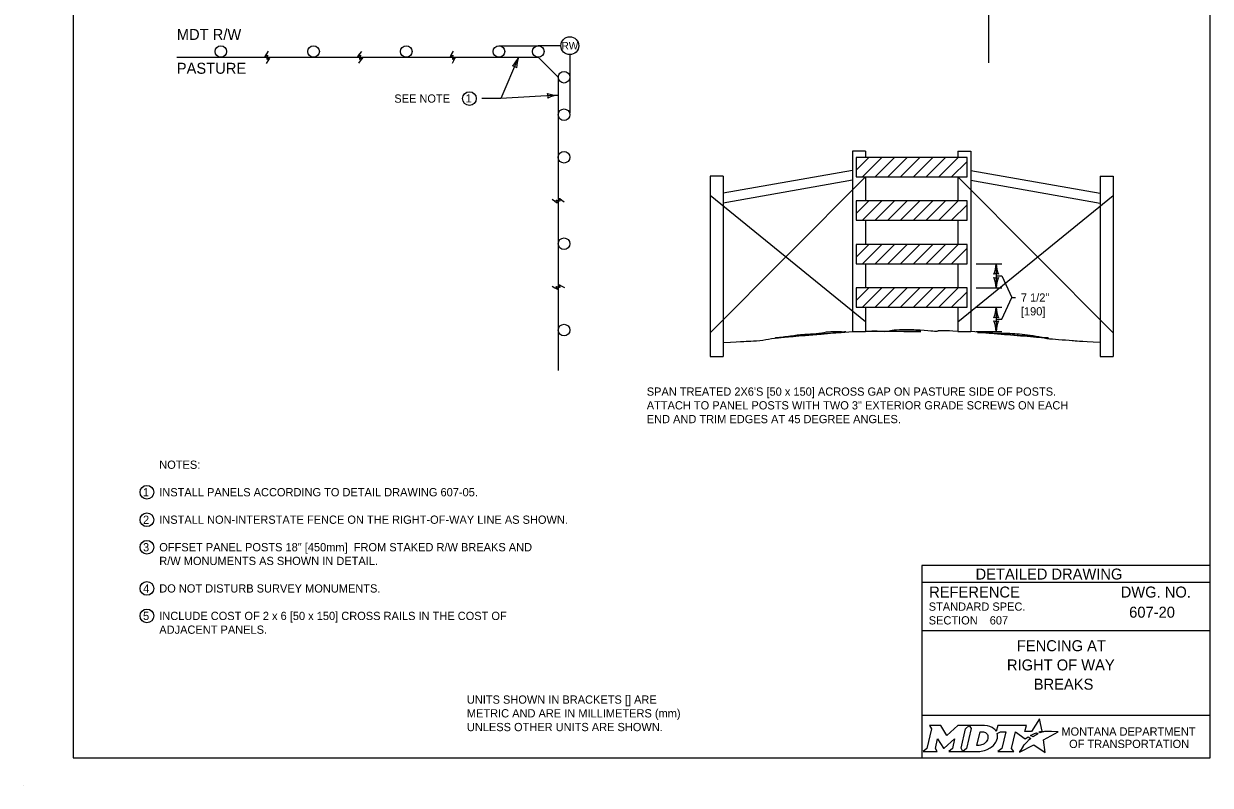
# Model space of a CAD drawing. Extents: x 49991.4 to 50021, y 49987.6 to 50011.4.
# Drawn here: x 49999.98 to 50008.61, y 49999.86 to 50005.41 of the extents above; entities that cross this region are included whole.
import ezdxf

# ---------------------------------------------------------------- set-up
doc = ezdxf.new("R2010")
doc.units = 0
for name, color, linetype in [('Default', 7, 'Continuous'), ('Level 1', 7, 'Continuous'), ('Level 2', 7, 'Continuous'), ('Level 3', 7, 'Continuous'), ('Level 5', 7, 'Continuous')]:
    doc.layers.add(name, color=color, linetype=linetype)

msp = doc.modelspace()

# ---------------------------------------------------------------- linework, layer by layer
at = {"layer": 'Default'}
msp.add_line((50003.9521, 50005.2464), (50003.9521, 50005.2464), dxfattribs=at)
msp.add_circle((50003.9521, 50005.2464), 0.0653, dxfattribs=at)
at = {"layer": 'Level 1'}
for p, q in [((50007.0001, 50006.2278), (50007.0001, 50005.1218)), ((50003.4364, 50005.2464), (50003.7227, 50005.2464)), ((50001.0908, 50005.162), (50003.7227, 50005.162)), ((50003.8677, 50005.017), (50003.7227, 50005.162)), ((50003.8677, 50005.017), (50003.8677, 50002.881)), ((50003.9521, 50005.017), (50003.9521, 50004.7565)), ((50006.0109, 50004.4791), (50006.0109, 50003.1666)), ((50006.1047, 50004.4791), (50006.0109, 50004.4791)), ((50006.13, 50004.4322), (50006.0378, 50004.34)), ((50006.2228, 50004.4322), (50006.0822, 50004.2916)), ((50006.1047, 50004.4791), (50006.1047, 50004.4322)), ((50006.3156, 50004.4322), (50006.175, 50004.2916)), ((50006.4084, 50004.4322), (50006.2678, 50004.2916)), ((50006.5012, 50004.4322), (50006.3606, 50004.2916)), ((50006.594, 50004.4322), (50006.4534, 50004.2916)), ((50006.6868, 50004.4322), (50006.5462, 50004.2916)), ((50006.7796, 50004.4322), (50006.639, 50004.2916)), ((50006.7776, 50004.4791), (50006.8713, 50004.4791)), ((50006.7776, 50004.4791), (50006.7776, 50004.4322)), ((50006.8713, 50004.4791), (50006.8713, 50003.1666)), ((50006.8445, 50004.4043), (50006.7318, 50004.2916)), ((50005.068, 50004.2962), (50004.9743, 50004.2962)), ((50004.9743, 50004.2962), (50004.9743, 50002.9837)), ((50004.9743, 50003.1564), (50006.1047, 50004.2916)), ((50006.0109, 50004.3384), (50005.068, 50004.1721)), ((50005.068, 50004.2962), (50005.068, 50002.9837)), ((50006.0109, 50004.267), (50005.068, 50004.1007)), ((50006.1047, 50004.2916), (50006.1047, 50004.1158)), ((50006.7776, 50004.2916), (50006.7776, 50004.1158)), ((50007.908, 50003.1564), (50006.7776, 50004.2916)), ((50006.8713, 50004.3384), (50007.8142, 50004.1721)), ((50006.8713, 50004.267), (50007.8142, 50004.1007)), ((50007.8142, 50004.2962), (50007.908, 50004.2962)), ((50007.8142, 50004.2962), (50007.8142, 50002.9837)), ((50007.908, 50004.2962), (50007.908, 50002.9837)), ((50006.1047, 50003.2364), (50004.9743, 50004.1556)), ((50006.13, 50004.1158), (50006.0378, 50004.0236)), ((50006.2228, 50004.1158), (50006.0822, 50003.9752)), ((50006.3156, 50004.1158), (50006.175, 50003.9752)), ((50006.4084, 50004.1158), (50006.2678, 50003.9752)), ((50006.5012, 50004.1158), (50006.3606, 50003.9752)), ((50006.594, 50004.1158), (50006.4534, 50003.9752)), ((50006.6868, 50004.1158), (50006.5462, 50003.9752)), ((50006.7796, 50004.1158), (50006.639, 50003.9752)), ((50006.8445, 50004.0879), (50006.7318, 50003.9752)), ((50006.7776, 50003.2364), (50007.908, 50004.1556)), ((50006.1047, 50003.9752), (50006.1047, 50003.7994)), ((50006.7776, 50003.9752), (50006.7776, 50003.7994)), ((50006.13, 50003.7994), (50006.0378, 50003.7072)), ((50006.2228, 50003.7994), (50006.0822, 50003.6588)), ((50006.3156, 50003.7994), (50006.175, 50003.6588)), ((50006.4084, 50003.7994), (50006.2678, 50003.6588)), ((50006.5012, 50003.7994), (50006.3606, 50003.6588)), ((50006.594, 50003.7994), (50006.4534, 50003.6588)), ((50006.6868, 50003.7994), (50006.5462, 50003.6588)), ((50006.7796, 50003.7994), (50006.639, 50003.6588)), ((50006.8445, 50003.7715), (50006.7318, 50003.6588)), ((50006.1047, 50003.6588), (50006.1047, 50003.483)), ((50006.7776, 50003.6588), (50006.7776, 50003.483)), ((50006.13, 50003.483), (50006.0378, 50003.3908)), ((50006.2228, 50003.483), (50006.0822, 50003.3424)), ((50006.3156, 50003.483), (50006.175, 50003.3424)), ((50006.4084, 50003.483), (50006.2678, 50003.3424)), ((50006.5012, 50003.483), (50006.3606, 50003.3424)), ((50006.594, 50003.483), (50006.4534, 50003.3424)), ((50006.6868, 50003.483), (50006.5462, 50003.3424)), ((50006.7796, 50003.483), (50006.639, 50003.3424)), ((50006.8445, 50003.4551), (50006.7318, 50003.3424)), ((50006.1047, 50003.3424), (50006.1047, 50003.1666)), ((50006.7776, 50003.3424), (50006.7776, 50003.1666)), ((50006.0109, 50003.1666), (50006.1047, 50003.1666)), ((50006.7776, 50003.1666), (50006.8713, 50003.1666)), ((50004.9743, 50002.9837), (50005.068, 50002.9837)), ((50007.8142, 50002.9837), (50007.908, 50002.9837)), ((49999.9766, 49999.8624), (49999.9766, 49999.8624))]:
    msp.add_line(p, q, dxfattribs=at)
for points in [[(50008.6146, 50011.2628), (50000.3356, 50011.2628), (50000.3356, 50000.0624), (50008.6146, 50000.0624)], [(50006.0378, 50004.4322), (50006.0378, 50004.2916), (50006.8445, 50004.2916), (50006.8445, 50004.4322)], [(50006.0378, 50004.1158), (50006.0378, 50003.9752), (50006.8445, 50003.9752), (50006.8445, 50004.1158)], [(50006.0378, 50003.7994), (50006.0378, 50003.6588), (50006.8445, 50003.6588), (50006.8445, 50003.7994)], [(50006.0378, 50003.483), (50006.0378, 50003.3424), (50006.8445, 50003.3424), (50006.8445, 50003.483)]]:
    msp.add_lwpolyline(points, close=True, dxfattribs=at)
for centre in [(50001.4114, 50005.2042), (50002.0864, 50005.2042), (50002.7614, 50005.2042), (50003.4364, 50005.2042), (50003.7227, 50005.2042), (50003.9099, 50005.017), (50003.9099, 50004.744), (50003.9098, 50004.4338), (50003.9099, 50003.8049), (50003.91, 50003.176)]:
    msp.add_circle(centre, 0.0422, dxfattribs=at)
for points in [[(50001.7556, 50005.2058), (50001.7337, 50005.164), (50001.7509, 50005.1769), (50001.7467, 50005.1466), (50001.7639, 50005.1594), (50001.7422, 50005.1174)], [(50002.4347, 50005.2053), (50002.4091, 50005.1658), (50002.4274, 50005.1769), (50002.4203, 50005.1472), (50002.4387, 50005.1583), (50002.4132, 50005.1185)], [(50003.1018, 50005.2062), (50003.0836, 50005.1627), (50003.0997, 50005.177), (50003.098, 50005.1464), (50003.1141, 50005.1607), (50003.096, 50005.117)], [(50003.8241, 50004.1286), (50003.8646, 50004.1044), (50003.8528, 50004.1223), (50003.8828, 50004.1164), (50003.8709, 50004.1343), (50003.9116, 50004.1103)], [(50003.8234, 50003.4948), (50003.8663, 50003.4752), (50003.8525, 50003.4918), (50003.883, 50003.4891), (50003.8693, 50003.5057), (50003.9124, 50003.4862)]]:
    msp.add_spline(points, degree=3, dxfattribs=at)
for points in [[(50005.068, 50003.0861), (50005.2257, 50003.0938), (50005.2638, 50003.0965), (50005.3597, 50003.1007), (50005.438, 50003.1194), (50005.546, 50003.131), (50005.6474, 50003.1474), (50005.7209, 50003.1464), (50005.8113, 50003.1608), (50005.8633, 50003.1685), (50005.9543, 50003.163), (50006.0109, 50003.1666), (50005.068, 50003.0861), (50006.0109, 50003.1666)], [(50006.7776, 50003.1666), (50006.7203, 50003.1698), (50006.6815, 50003.1712), (50006.6377, 50003.1706), (50006.6366, 50003.1706), (50006.632, 50003.1695), (50006.6241, 50003.1662), (50006.6101, 50003.1655), (50006.5111, 50003.176), (50006.3666, 50003.1804), (50006.29, 50003.1724), (50006.2627, 50003.1638), (50006.2187, 50003.1645), (50006.1633, 50003.1707), (50006.1047, 50003.1666), (50006.7776, 50003.1666), (50006.1047, 50003.1666)], [(50007.8142, 50003.0861), (50007.6565, 50003.0938), (50007.6185, 50003.0965), (50007.5051, 50003.1066), (50007.4242, 50003.1104), (50007.3479, 50003.132), (50007.2604, 50003.1428), (50007.1917, 50003.1489), (50007.1175, 50003.1523), (50007.0314, 50003.1498), (50006.927, 50003.1571), (50006.8713, 50003.1666), (50007.8142, 50003.0861), (50006.8713, 50003.1666)]]:
    msp.add_open_spline(points, degree=3, dxfattribs=at)
at = {"layer": 'Level 2'}
for p, q in [((50008.6146, 50001.4624), (50006.5146, 50001.4624)), ((50006.5146, 50001.4624), (50006.5146, 50000.0624)), ((50008.6146, 50001.3374), (50006.5146, 50001.3374)), ((50008.2507, 50001.1223), (50008.2507, 50001.1223)), ((50008.6146, 50000.9874), (50006.5146, 50000.9874)), ((50007.0089, 50001.0629), (50007.0089, 50001.0629)), ((50007.5646, 50000.7383), (50007.5646, 50000.7383)), ((50008.6146, 50000.3693), (50006.5146, 50000.3693))]:
    msp.add_line(p, q, dxfattribs=at)
for points in [[(50006.5701, 50000.2974), (50006.5842, 50000.274), (50006.5507, 50000.1307), (50006.525, 50000.1082), (50006.6266, 50000.1082), (50006.6131, 50000.131), (50006.6293, 50000.2011), (50006.673, 50000.1321), (50006.6783, 50000.1321), (50006.7534, 50000.2016), (50006.737, 50000.1305), (50006.7123, 50000.1085), (50006.8139, 50000.1085), (50006.8001, 50000.1318), (50006.8333, 50000.2742)], [(50006.8333, 50000.2742), (50006.8586, 50000.2974), (50006.7762, 50000.2974), (50006.6966, 50000.2244), (50006.6521, 50000.2971), (50006.5701, 50000.2974)], [(50006.9722, 50000.2974), (50006.8586, 50000.2974), (50006.8733, 50000.2745), (50006.8394, 50000.1307), (50006.8139, 50000.1085), (50006.9245, 50000.1085)], [(50007.3771, 50000.2447), (50007.3668, 50000.2503), (50007.3784, 50000.2531), (50007.39, 50000.2551), (50007.3726, 50000.3452), (50007.3131, 50000.2539), (50007.2658, 50000.2532), (50007.2761, 50000.2973), (50007.0669, 50000.2974), (50007.0568, 50000.2549), (50007.051, 50000.2632)], [(50006.9962, 50000.2107), (50006.995, 50000.2026), (50006.9918, 50000.1933), (50006.9876, 50000.1851), (50006.982, 50000.1776), (50006.9755, 50000.1707), (50006.9676, 50000.1644), (50006.9593, 50000.1597), (50006.9502, 50000.1558), (50006.9411, 50000.1535), (50006.9319, 50000.1526), (50006.916, 50000.1526), (50006.9396, 50000.2526), (50006.9556, 50000.2526), (50006.9632, 50000.252), (50006.9708, 50000.2501), (50006.9774, 50000.2471), (50006.9835, 50000.2429), (50006.9883, 50000.2379), (50006.992, 50000.2319), (50006.9947, 50000.2257), (50006.9963, 50000.2183), (50006.9963, 50000.2153), (50006.9962, 50000.2107)], [(50007.0636, 50000.2383), (50007.0882, 50000.2514), (50007.1251, 50000.2514), (50007.0965, 50000.1309), (50007.069, 50000.1082), (50007.1852, 50000.1082), (50007.1682, 50000.1311), (50007.1964, 50000.2513), (50007.2677, 50000.1996), (50007.2888, 50000.2147), (50007.3085, 50000.2038)], [(50007.2527, 50000.1479), (50007.2374, 50000.1235), (50007.2327, 50000.116), (50007.2269, 50000.1074), (50007.2246, 50000.1031), (50007.3299, 50000.1562), (50007.4138, 50000.1011), (50007.4007, 50000.1938), (50007.5076, 50000.2522), (50007.4583, 50000.253), (50007.4282, 50000.2534), (50007.4074, 50000.2537), (50007.4006, 50000.2522), (50007.3957, 50000.251), (50007.3873, 50000.2487), (50007.3771, 50000.2447)], [(50007.3267, 50000.2171), (50007.3243, 50000.2154), (50007.306, 50000.225), (50007.3163, 50000.2307), (50007.3204, 50000.2329), (50007.329, 50000.2369), (50007.3347, 50000.2395), (50007.3426, 50000.2425), (50007.3499, 50000.2452), (50007.3617, 50000.2378), (50007.3577, 50000.2357), (50007.3531, 50000.2332), (50007.3489, 50000.231), (50007.3439, 50000.2281), (50007.342, 50000.227), (50007.3393, 50000.2254), (50007.3368, 50000.224), (50007.3345, 50000.2224), (50007.3319, 50000.2206), (50007.3292, 50000.2188), (50007.3267, 50000.2171)], [(50006.9702, 50000.1158), (50006.9786, 50000.1184), (50006.9916, 50000.1238), (50007.012, 50000.1348)], [(50007.2666, 50000.164), (50007.2666, 50000.164)]]:
    msp.add_lwpolyline(points, dxfattribs=at)
for centre in [(50003.2213, 50004.8615), (50000.8732, 50001.9955), (50000.8732, 50001.7954), (50000.8732, 50001.5953), (50000.8732, 50001.2951), (50000.8732, 50001.0953)]:
    msp.add_circle(centre, 0.05, dxfattribs=at)
for centre, radius, start, end in [((50006.9953, 50000.219), 0.0709, 339.53292, 15.85821), ((50006.9513, 50000.2363), 0.1183, 300.91025, 339.13831)]:
    msp.add_arc(centre, radius, start, end, dxfattribs=at)
for centre, major_axis, ratio, start_param, end_param in [((50006.9701, 50000.25), (0.0834, -0.0037), 0.568097, 0.61298, 1.570796), ((50007.0257, 50000.2573), (0.0361, -0.0295), 0.469099, 1.225588, 1.570796), ((50007.2974, 50000.1941), (-0.0112, -0.0097), 0.021651, 3.157348, 6.283185), ((50006.9248, 50000.2568), (0, 0.1484), 0.987302, 3.139398, 3.456847), ((50007.2597, 50000.1559), (-0.00694, -0.00806), 0.008222, 0, 3.137361), ((50007.2764, 50000.1742), (-0.0098, -0.0102), 0.016458, 3.141593, 6.279097)]:
    msp.add_ellipse(centre, major_axis=major_axis, ratio=ratio, start_param=start_param, end_param=end_param, dxfattribs=at)
at = {"layer": 'Level 3'}
for p, q in [((50003.8868, 50005.2464), (50003.7227, 50005.2464)), ((50003.5795, 50005.162), (50003.45, 50004.8615)), ((50003.9521, 50005.181), (50003.9521, 50005.017)), ((50003.8677, 50004.8867), (50003.45, 50004.8615)), ((50003.45, 50004.8615), (50003.3113, 50004.8615)), ((50006.9113, 50003.6588), (50007.0961, 50003.6588)), ((50007.0561, 50003.6588), (50007.0561, 50003.483)), ((50006.9113, 50003.483), (50007.0961, 50003.483)), ((50007.169, 50003.4127), (50007.1959, 50003.4127)), ((50006.9113, 50003.3424), (50007.0961, 50003.3424)), ((50007.0561, 50003.3424), (50007.0561, 50003.1666)), ((50006.9113, 50003.1666), (50007.0961, 50003.1666))]:
    msp.add_line(p, q, dxfattribs=at)
for points in [[(50007.0561, 50003.5709), (50007.0961, 50003.5709), (50007.169, 50003.4127)], [(50007.0561, 50003.2545), (50007.0961, 50003.2545), (50007.169, 50003.4127)]]:
    msp.add_lwpolyline(points, dxfattribs=at)
for centre, radius, start, end in [((50003.3792, 50005.2583), 0.2223, 314.14194, 334.32545), ((50003.7978, 50005.0804), 0.233, 159.51324, 178.76309), ((50003.5288, 50005.0442), 0.0548, 48.82475, 84.54711), ((50003.8635, 50005.109), 0.2223, 250.91163, 271.09514), ((50003.7397, 50004.879), 0.0548, 345.59444, 21.3168), ((50003.8932, 50004.6551), 0.233, 96.28293, 115.53278), ((50006.8339, 50003.6679), 0.2223, 337.45601, 357.63952), ((50007.2888, 50003.6703), 0.233, 182.82731, 202.07716), ((50007.0561, 50003.5305), 0.0548, 72.13882, 107.86118), ((50007.0561, 50003.6112), 0.0548, 252.13882, 287.86118), ((50006.8234, 50003.4715), 0.233, 2.82731, 22.07716), ((50007.2782, 50003.4738), 0.2223, 157.45601, 177.63952), ((50006.8339, 50003.3515), 0.2223, 337.45601, 357.63952), ((50007.2888, 50003.3538), 0.233, 182.82731, 202.07716), ((50007.0561, 50003.2141), 0.0548, 72.13882, 107.86118), ((50007.0561, 50003.2948), 0.0548, 252.13882, 287.86118), ((50006.8234, 50003.1551), 0.233, 2.82731, 22.07716), ((50007.2782, 50003.1574), 0.2223, 157.45601, 177.63952)]:
    msp.add_arc(centre, radius, start, end, dxfattribs=at)

# ---------------------------------------------------------------- texts
at = {"layer": 'Level 2'}
for s, height, p in [('MDT R/W', 0.08, (50001.0908, 50005.2884)), ('RW', 0.054, (50003.8925, 50005.2192)), ('PASTURE', 0.08, (50001.0908, 50005.042)), ('SEE NOTE', 0.06, (50002.6744, 50004.8315)), ('1', 0.06, (50003.1937, 50004.833)), ('7 1/2"', 0.06, (50007.2359, 50003.3827)), ('[190]', 0.06, (50007.2359, 50003.2827)), ("SPAN TREATED 2X6'S [50 x 150] ACROSS GAP ON PASTURE SIDE OF POSTS. ", 0.06, (50004.5122, 50002.6983)), ('ATTACH TO PANEL POSTS WITH TWO 3" EXTERIOR GRADE SCREWS ON EACH ', 0.06, (50004.5122, 50002.5983)), ('END AND TRIM EDGES AT 45 DEGREE ANGLES.', 0.06, (50004.5122, 50002.4983)), ('NOTES:', 0.06004, (50000.9632, 50002.166)), ('1', 0.06, (50000.8439, 50001.9654)), ('INSTALL PANELS ACCORDING TO DETAIL DRAWING 607-05.', 0.060039, (50000.9632, 50001.9659)), ('2', 0.06, (50000.8452, 50001.7654)), ('INSTALL NON-INTERSTATE FENCE ON THE RIGHT-OF-WAY LINE AS SHOWN.', 0.060039, (50000.9632, 50001.7658)), ('3', 0.06, (50000.8451, 50001.5653)), ('OFFSET PANEL POSTS 18" [450mm]  FROM STAKED R/W BREAKS AND ', 0.060039, (50000.9632, 50001.5656)), ('R/W MONUMENTS AS SHOWN IN DETAIL.', 0.060039, (50000.9632, 50001.4656)), ('4', 0.06, (50000.8464, 50001.2651)), ('DO NOT DISTURB SURVEY MONUMENTS.', 0.060039, (50000.9632, 50001.2654)), ('REFERENCE', 0.08, (50006.5682, 50001.229)), ('DWG. NO.', 0.08, (50007.9624, 50001.229)), ('STANDARD SPEC.', 0.06, (50006.5649, 50001.133)), ('607-20', 0.08, (50008.0241, 50001.0823)), ('5', 0.06, (50000.8454, 50001.0653)), ('INCLUDE COST OF 2 x 6 [50 x 150] CROSS RAILS IN THE COST OF', 0.060039, (50000.9632, 50001.0653)), ('SECTION', 0.06, (50006.5649, 50001.033)), ('607', 0.06, (50007.0089, 50001.0329)), ('ADJACENT PANELS.', 0.060039, (50000.9632, 50000.9652)), ('FENCING AT', 0.08, (50007.2068, 50000.8383)), ('RIGHT OF WAY', 0.08, (50007.1345, 50000.6983)), ('BREAKS', 0.08, (50007.3296, 50000.5583)), ('UNITS SHOWN IN BRACKETS [] ARE', 0.06, (50003.2027, 50000.4563)), ('METRIC AND ARE IN MILLIMETERS (mm)', 0.06, (50003.2027, 50000.3563)), ('UNLESS OTHER UNITS ARE SHOWN.', 0.06, (50003.2027, 50000.2563)), ('MONTANA DEPARTMENT', 0.06, (50007.5308, 50000.2236)), ('OF TRANSPORTATION', 0.06, (50007.587, 50000.1336))]:
    msp.add_text(s, height=height, dxfattribs=at).set_placement(p)
at = {"layer": 'Level 5'}
msp.add_text('DETAILED DRAWING', height=0.0799, dxfattribs=at).set_placement((50006.9063, 50001.3599))

doc.saveas('drawing.dxf')
